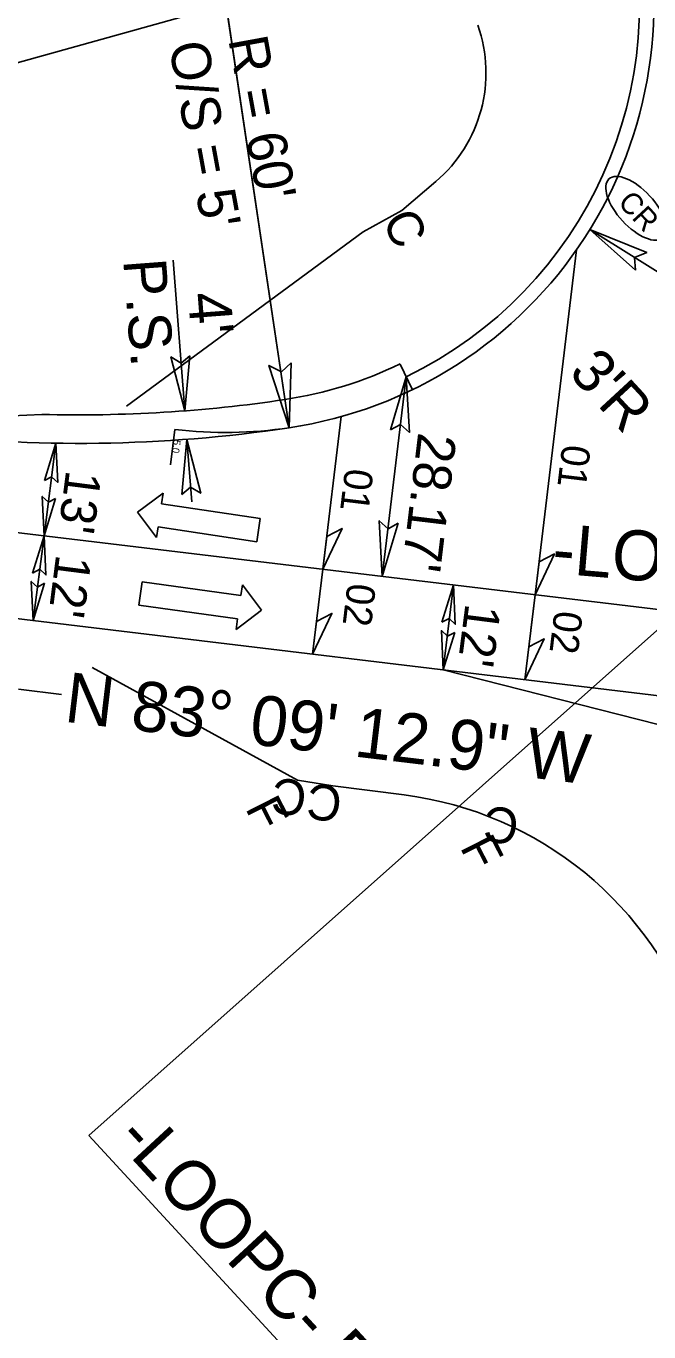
# Model space of a CAD drawing. Extents: x 1702862 to 1704514, y 793768 to 796215.
# Drawn here: x 1703745.4 to 1703832.7, y 794386.1 to 794569.2 of the extents above; entities that cross this region are included whole.
import ezdxf

# ---------------------------------------------------------------- set-up
doc = ezdxf.new("R2010")
doc.units = 0
for name, color, linetype in [('Prop Conc 2ft 6in Curb and Gutter', 7, 'Continuous'), ('Prop Dimension', 7, 'Continuous'), ('Prop Dimension Text', 7, 'Continuous'), ('Prop DSN Text', 7, 'Continuous'), ('Prop EOT', 7, 'Continuous'), ('Prop Guardrail', 7, 'Continuous'), ('Prop Horizontal Alignment', 7, 'Continuous'), ('Prop Horizontal Alignment Curve and Spiral Data', 7, 'Continuous'), ('Prop Horizontal Alignment Direction Label', 7, 'Continuous'), ('Prop Horizontal Alignment Station Label', 7, 'Continuous'), ('Prop Horizontal Alignment Tick Small', 7, 'Continuous'), ('Prop Lane Arrow CELL', 7, 'Continuous'), ('Prop Lane Lines', 7, 'Continuous'), ('Prop Paved Shoulder', 7, 'Continuous'), ('Prop SS Cut Line', 7, 'Continuous'), ('Prop SS Fill Line', 7, 'Continuous'), ('Prop SS Misc', 7, 'Continuous'), ('Prop SS Transition Line', 7, 'Continuous'), ('Prop Superelevation  Arrow CELL', 7, 'Continuous'), ('Prop Superelevation Label', 7, 'Continuous'), ('Prop Terminator CELL', 7, 'Continuous'), ('Prop WCR CELL', 7, 'Continuous')]:
    doc.layers.add(name, color=color, linetype=linetype)

msp = doc.modelspace()

# ---------------------------------------------------------------- linework, layer by layer
at = {"layer": 'Prop Conc 2ft 6in Curb and Gutter'}
msp.add_arc((1703773.4, 794572.2), 58, 295.8355, 15.5759, dxfattribs=at)
at = {"layer": 'Prop Dimension'}
for p, q in [((1703752.73, 794710.66), (1703782.26, 794512.85)), ((1703638.54, 794534.6), (1703831.2, 794588.31)), ((1703773.4, 794572.2), (1703782.26, 794512.85)), ((1703824.44, 794540.66), (1703849.88, 794524.75)), ((1703767.61, 794515.23), (1703766, 794536.37)), ((1703795.32, 794492.02), (1703798.68, 794519.99)), ((1703766.23, 794512.63), (1703765.63, 794507.66)), ((1703768.58, 794502.47), (1703767.91, 794511.23)), ((1703805.29, 794490.82), (1703803.86, 794478.91))]:
    msp.add_line(p, q, dxfattribs=at)
msp.add_arc((1703773.4, 794572.2), 60, 263.1332, 278.4921, dxfattribs=at)
at = {"layer": 'Prop DSN Text'}
for p, q in [((1703749.54, 794510.69), (1703747.87, 794497.72)), ((1703747.87, 794497.72), (1703746.34, 794485.81))]:
    msp.add_line(p, q, dxfattribs=at)
at = {"layer": 'Prop EOT'}
msp.add_line((1703844.62, 794474.01), (1703740.76, 794486.48), dxfattribs=at)
for centre, radius, start, end in [((1702989.11, 794124.65), 1018, 14.75888, 42.70907), ((1703773.4, 794572.2), 60, 278.4921, 15.5759), ((1703752.73, 794710.66), 200, 263.1332, 278.4921)]:
    msp.add_arc(centre, radius, start, end, dxfattribs=at)
at = {"layer": 'Prop Guardrail'}
msp.add_arc((1702988.97, 794124.56), 1026.16, 25.61718, 37.4674, dxfattribs=at)
at = {"layer": 'Prop Horizontal Alignment'}
msp.add_line((1703836.77, 794487.04), (1703719.97, 794501.07), dxfattribs=at)
msp.add_arc((1702989.11, 794124.65), 1000, 351.25916, 42.70907, dxfattribs=at)
at = {"layer": 'Prop Horizontal Alignment Curve and Spiral Data'}
msp.add_line((1703754.16, 794413.63), (1703829.87, 794331.61), dxfattribs=at)
at = {"layer": 'Prop Horizontal Alignment Direction Label'}
msp.add_line((1703750.3, 794475.45), (1703744.31, 794476.19), dxfattribs=at)
at = {"layer": 'Prop Horizontal Alignment Station Label'}
msp.add_line((1703836.77, 794487.04), (1703754.16, 794413.63), dxfattribs=at)
at = {"layer": 'Prop Horizontal Alignment Tick Small'}
msp.add_line((1703816.75, 794489.45), (1703816.16, 794484.48), dxfattribs=at)
at = {"layer": 'Prop Lane Arrow CELL'}
for p, q in [((1703760.99, 794501.01), (1703764.59, 794503.7)), ((1703764.59, 794503.7), (1703764.36, 794502.21)), ((1703764.36, 794502.21), (1703778.2, 794500.11)), ((1703763.64, 794497.47), (1703760.99, 794501.01)), ((1703778.2, 794500.11), (1703777.71, 794496.85)), ((1703763.87, 794498.95), (1703763.64, 794497.47)), ((1703777.71, 794496.85), (1703763.87, 794498.95)), ((1703761.16, 794487.98), (1703761.62, 794491.25)), ((1703761.62, 794491.25), (1703775.48, 794489.32)), ((1703775.48, 794489.32), (1703775.69, 794490.81)), ((1703775.69, 794490.81), (1703778.38, 794487.3)), ((1703775.03, 794486.05), (1703761.16, 794487.98)), ((1703778.38, 794487.3), (1703774.82, 794484.57)), ((1703774.82, 794484.57), (1703775.03, 794486.05))]:
    msp.add_line(p, q, dxfattribs=at)
at = {"layer": 'Prop Lane Lines'}
for radius, start, end in [(1006, 0.00687, 42.70907), (994, 359.40932, 42.70907), (980, 359.40932, 42.70907), (968, 17.6382, 31.00789)]:
    msp.add_arc((1702989.11, 794124.65), radius, start, end, dxfattribs=at)
at = {"layer": 'Prop Paved Shoulder'}
for p, q in [((1703797.8, 794521.79), (1703799.55, 794518.19)), ((1703747.55, 794514.73), (1703718.97, 794513.28)), ((1703803.86, 794478.91), (1703834.03, 794471.26))]:
    msp.add_line(p, q, dxfattribs=at)
for centre, radius, start, end in [((1703773.4, 794572.2), 56, 278.4921, 295.8355), ((1703752.73, 794710.66), 196, 268.4875, 278.4921)]:
    msp.add_arc(centre, radius, start, end, dxfattribs=at)
at = {"layer": 'Prop SS Cut Line'}
for p, q in [((1703802.82, 794547.39), (1703798.04, 794543.32)), ((1703798.04, 794543.32), (1703792.65, 794540.32)), ((1703788.36, 794462.65), (1703783.41, 794463.43))]:
    msp.add_line(p, q, dxfattribs=at)
at = {"layer": 'Prop SS Fill Line'}
msp.add_line((1703788.36, 794462.65), (1703783.41, 794463.43), dxfattribs=at)
msp.add_arc((1703792.04, 794411.78), 50, 18.6944, 82.73, dxfattribs=at)
at = {"layer": 'Prop SS Transition Line'}
for p, q in [((1703792.65, 794540.32), (1703759.46, 794515.89)), ((1703783.41, 794463.43), (1703754.61, 794479.23)), ((1703798.37, 794461.37), (1703788.36, 794462.65))]:
    msp.add_line(p, q, dxfattribs=at)
msp.add_arc((1703789.86, 794562.62), 20, 310.3906, 19.4922, dxfattribs=at)
at = {"layer": 'Prop Superelevation  Arrow CELL'}
for p, q in [((1703822.56, 794537.79), (1703816.75, 794489.45)), ((1703789.53, 794514.41), (1703786.97, 794493.02)), ((1703786.97, 794493.02), (1703785.54, 794481.11)), ((1703816.75, 794489.45), (1703815.32, 794477.53))]:
    msp.add_line(p, q, dxfattribs=at)
for points in [[(1703786.97, 794493.02), (1703789.67, 794498.74), (1703787.52, 794497.61)], [(1703816.75, 794489.45), (1703819.45, 794495.16), (1703817.3, 794494.04)], [(1703785.54, 794481.11), (1703788.24, 794486.83), (1703786.09, 794485.7)], [(1703815.32, 794477.53), (1703818.02, 794483.25), (1703815.87, 794482.12)]]:
    msp.add_lwpolyline(points, close=True, dxfattribs=at)
at = {"layer": 'Prop Terminator CELL'}
for points in [[(1703830.81, 794534.97), (1703824.44, 794540.66), (1703832.41, 794537.44), (1703830.7, 794536.74)], [(1703768.34, 794522.95), (1703767.61, 794515.23), (1703765.67, 794522.79), (1703767.1, 794521.92)], [(1703782.54, 794521.98), (1703782.26, 794512.85), (1703779.42, 794521.59), (1703781.16, 794520.68)], [(1703796.46, 794512.55), (1703798.68, 794519.99), (1703799.11, 794512.19), (1703797.87, 794513.33)], [(1703767.18, 794503.5), (1703767.91, 794511.23), (1703769.85, 794503.66), (1703768.42, 794504.54)], [(1703747.93, 794505.45), (1703749.54, 794510.69), (1703749.8, 794505.18), (1703748.94, 794505.98)], [(1703749.49, 794502.95), (1703747.87, 794497.72), (1703747.62, 794503.22), (1703748.48, 794502.42)], [(1703797.54, 794499.46), (1703795.32, 794492.02), (1703794.88, 794499.82), (1703796.12, 794498.69)], [(1703746.26, 794492.48), (1703747.87, 794497.72), (1703748.13, 794492.21), (1703747.27, 794493.01)], [(1703747.96, 794491.05), (1703746.34, 794485.81), (1703746.08, 794491.32), (1703746.95, 794490.51)], [(1703803.68, 794485.58), (1703805.29, 794490.82), (1703805.55, 794485.31), (1703804.68, 794486.12)], [(1703805.47, 794484.14), (1703803.86, 794478.91), (1703803.6, 794484.42), (1703804.46, 794483.61)]]:
    msp.add_lwpolyline(points, close=True, dxfattribs=at)
at = {"layer": 'Prop WCR CELL'}
msp.add_ellipse((1703830.91, 794543.62), major_axis=(3.8, -4.12), ratio=0.462467, dxfattribs=at)

# ---------------------------------------------------------------- texts
at = {"layer": 'Prop Dimension Text'}
for s, height, rotation, p in [("R = 60'", 5.5, 280.3746, (1703773.7, 794567.3)), ("O/S = 5'", 5.5, 280.3746, (1703765.35, 794566.56)), ('P.S.', 6, 274.3541, (1703758.97, 794536.36)), ("4'", 6, 274.3541, (1703768.05, 794531.66)), ("3'R", 6, 312.7091, (1703821.3, 794520.47)), ('5.0', 1, 263.1332, (1703766.05, 794511.2)), ("28.17'", 5.4, 263.1536, (1703800.37, 794512.31)), ("13'", 5, 262.672, (1703750.99, 794507.02)), ("12'", 5, 262.672, (1703749.59, 794495.21)), ("12'", 5, 262.672, (1703807, 794488.32))]:
    msp.add_text(s, height=height, rotation=rotation, dxfattribs=at).set_placement(p)
at = {"layer": 'Prop Horizontal Alignment Direction Label'}
for s, rotation, p in [('-LOOPC-', 355.1313, (1703818.98, 794492.49)), ('N 83%%d 09\' 12.9" W', 353.1536, (1703750.58, 794471.66))]:
    msp.add_text(s, height=7, rotation=rotation, dxfattribs=at).set_placement(p)
at = {"layer": 'Prop Horizontal Alignment Station Label'}
msp.add_text('-LOOPC- PT 10+79.84', height=7, rotation=312.7091, dxfattribs=at).set_placement((1703757.71, 794413.01))
at = {"layer": 'Prop SS Misc'}
for s, rotation, p in [('C', 296.9289, (1703795.2, 794541.88)), ('C', 173.1536, (1703784.94, 794463.25)), ('C', 173.1536, (1703789.88, 794462.47)), ('F', 296.9289, (1703776.03, 794459.54)), ('C', 173.1536, (1703814.68, 794459.3)), ('F', 296.9289, (1703806.15, 794454.06))]:
    msp.add_text(s, height=5, rotation=rotation, dxfattribs=at).set_placement(p)
at = {"layer": 'Prop Superelevation Label'}
for s, p in [('01', (1703820.58, 794510.62)), ('01', (1703790.11, 794507.28)), ('02', (1703790.46, 794491.19)), ('02', (1703819.47, 794487.33))]:
    msp.add_text(s, height=4, rotation=263.1536, dxfattribs=at).set_placement(p)
at = {"layer": 'Prop WCR CELL'}
msp.add_text('CR', height=3, rotation=312.7091, dxfattribs=at).set_placement((1703828.22, 794544.35))

doc.saveas('drawing.dxf')
